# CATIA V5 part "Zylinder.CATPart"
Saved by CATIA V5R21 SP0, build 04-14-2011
Part number: Zylinder
Bounding box of the stored display mesh (mm): x -66 to 82.029, y 0 to 58, z -12.144 to 145
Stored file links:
  C:\Users\otto\Desktop\Rotax 600\CAD Modell\Zylinder.CATPart
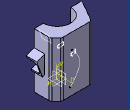
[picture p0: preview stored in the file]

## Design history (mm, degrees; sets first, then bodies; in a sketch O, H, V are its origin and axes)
Body1 (main body)
  Sketch1 on xy-plane, origin (0, 0, 0), H (1, 0, 0), V (0, 1, 0)
    arc A1 centre (0, 0) radius 36 from (36, 0) to (-36, 0) ccw
    point P1 (36, 0)
    line L1 (36, 0) -> (61, 0)
    line L2 (61, 0) -> (61, 39.1299)
    point P3 (61, 42.4437)
    line L3 (58.6569, 44.7868) -> (47.7868, 55.6569)
    point P4 (45.4437, 58)
    line L4 (42.1299, 58) -> (-27.8949, 58)
    line L5 (-34.8231, 54) -> (-66, 0)
    point P5 (-66, 0)
    line L6 (-66, 0) -> (-36, 0)
    arc A2 centre (-27.8949, 50) radius 8 from (-34.8231, 54) to (-27.8949, 58) cw
    arc A3 centre (42.1299, 50) radius 8 from (47.7868, 55.6569) to (42.1299, 58) ccw
    arc A4 centre (53, 39.1299) radius 8 from (61, 39.1299) to (58.6569, 44.7868) ccw
    radius A1 = 36
    distance A1 L4 = 22
    length L6 = 30
    length L1 = 25
    angle L3 L2 = 45
    angle L5 L4 = 60
    radius A2 = 8
    distance P3 P4 = 22
    radius A3 = 8
    radius A4 = 8
    coincidence: P1 H, P5 H, L3 P4, L4 P4, L2 P3, L3 P3
    horizontal: L1 H, L4 H, L6 H
    vertical: L2 V
    tangency: A2 L5, A2 L4, A3 L3, A3 L4, A4 L2, A4 L3
  Pad1: profile Sketch1, direction (0, 0, 1), length 145
  Sketch2 on face of Pad1 from Sketch1.L1, origin (0, 0, 0), H (1, 0, 0), V (0, 0, 1)
    line L1 (61, 100.9401) -> (82.0291, 93.2862)
    point P1 (61, 100.9401)
    line L2 (82.0291, 93.2862) -> (66.6382, 51)
    point P3 (66.6382, 51)
    line L3 (66.6382, 51) -> (61, 53.0521)
    point P4 (61, 53.0521)
    reference projected line E1 (61, 0) -> (61, 145) from edge [face of Pad1 from Sketch1.L2 | face of Pad1 from Sketch1.L1]
    reference projected line E2 (61, 0) -> (61, 145) from edge [face of Pad1 from Sketch1.L2 | face of Pad1 from Sketch1.L1]
    reference projected line E3 (61, 0) -> (61, 145) from edge [face of Pad1 from Sketch1.L2 | face of Pad1 from Sketch1.L1]
    line L4 (61, 53.0521) -> (61, 100.9401)
    point P5 (61, 100.9401)
    length L2 = 45
    angle L1 E3 = 110
    length L3 = 6
    distance P3 H = 51
    perpendicularity: L2 L1
    parallelism: L3 L1
    coincidence: E1 P4, P1 E2, P5 L1, P1 P5
  Pad2: profile Sketch2, direction (0, 1, 0), length 28
  Sketch3 on face of Pad2 from Sketch2.L2, origin (42.4519, 0, -15.4512), H (0, 1, 0), V (0.342, 0, 0.9397)
    point P1 (0, 76.2161)
    line L1 (0, 76.2161) -> (19, 76.2161)
    arc A1 centre (19, 82.2161) radius 6 from (19, 76.2161) to (25, 82.2161) ccw
    point P5 (25, 98.2157)
    arc A2 centre (13, 98.2157) radius 12 from (25, 98.2157) to (13, 110.2157) ccw
    line L2 (13, 110.2157) -> (0, 110.2157)
    point P8 (0, 110.2157)
    construction line L3 (12.1568, 93.2159) -> (-8.8602, 93.2159)
    reference projected line E1 (0, 70.7159) -> (28, 70.7159) from edge [face of Pad2 from Sketch2.L3 | face of Pad2 from Sketch2.L2]
    reference projected line E2 (0, 115.7159) -> (28, 115.7159) from edge [face of Pad2 from Sketch2.L2 | face of Pad2 from Sketch2.L1]
    line L4 (25, 82.2161) -> (25, 98.2157)
    point P11 (25, 98.2157)
    reference projected line E3 (0, 73.5245) -> (0, 118.5245) from edge [face of Pad2 from Sketch2.L2 | start face of Pad2]
    line L5 (0, 76.2161) -> (0, 110.2157)
    radius A2 = 12
    radius A1 = 6
    distance L2 L1 = 33.9996
    distance L4 E3 = 25
    coincidence: P1 V, P8 V, P11 P5
    horizontal: L1 H, L2 H, L3 H
    tangency: A1 L1, A2 L2, L4 A1, L4 A2
    symmetry: E1 E2 L3, L1 L2 L3
    vertical: L4 V, L5 V
  Plane1: type Offset, RefPlane face of Pad2 from Sketch2.L2, Offset -54, reversed
  Pocket1: profile Sketch3, direction (-0.9397, 0, 0.342), through (limit type 6)
  DatumCurve1
  DatumCurve2
  Sketch4 on face of Pad2, origin (0, 0, 0), H (1, 0, 0), V (0, 0, 1)
    point P1 (-17, 76)
    line L1 (-15, 76) -> (-4, 76)
    line L2 (-2, 74) -> (-2, 70)
    line L3 (-4, 68) -> (-15, 68)
    line L4 (-17, 70) -> (-17, 74)
    point P2 (-2, 76)
    point P3 (-2, 68)
    reference projected line E1 through (0, 0) direction (0, 1) from axis of face of Pad1 from Sketch1.A1
    arc A1 centre (-4, 74) radius 2 from (-4, 76) to (-2, 74) cw
    arc A2 centre (-4, 70) radius 2 from (-2, 70) to (-4, 68) cw
    arc A3 centre (-15, 70) radius 2 from (-15, 68) to (-17, 70) cw
    arc A4 centre (-15, 74) radius 2 from (-17, 74) to (-15, 76) cw
    reference projected line E2 (35.95, 68) -> (-35.95, 68) from edge of DatumCurve2
    distance L2 E1 = 2
    distance P1 P2 = 15
    distance P2 P3 = 8
    radius A1 = 2
    radius A2 = 2
    radius A3 = 2
    radius A4 = 2
    horizontal: L1 H, L3 H
    vertical: L2 V, L4 V
    coincidence: L1 P2, L2 P2, L2 P3, L3 P3, L4 P1, L1 P1, L3 E2
    tangency: A1 L1, A1 L2, A2 L2, A2 L3, A3 L3, A3 L4, A4 L4, A4 L1
  Plane2: type Offset, RefPlane yz-plane, Offset -10
  Develop1
  Sketch5 on Plane2, origin (-10, 0, 0), H (0, 1, 0), V (0, 0, 1)
    spline S1 through (30.0157, 74.9351) (44.0512, 71.7448) (41.4192, 24.7217) (24.5907, -12.1444)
